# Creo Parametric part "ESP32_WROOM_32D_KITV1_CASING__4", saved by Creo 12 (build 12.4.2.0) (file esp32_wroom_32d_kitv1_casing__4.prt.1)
Units: Custom; MM, KILOGRAM, SECS

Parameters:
  PTC_WM_ITERATION = "0"
  PTC_WM_VERSION = "-.0"
  PTC_WM_LIFECYCLE_STATE = "In Work"
  PTC_WM_LIFECYCLE = "MO_CADDocument"
  PTC_WM_CREATED_BY = "Maximilian Roepper (Z0017RMS: MO)"
  PTC_WM_CREATED_ON = "18-Sep-26 11:36:42 AM"
  PTC_WM_MODIFIED_BY = "Maximilian Roepper (Z0017RMS: MO)"
  PTC_WM_MODIFIED_ON = "18-Sep-26 11:36:46 AM"
  PDMLINKNUMBER = "PDM000071455080"
  PTC_WM_NAME = "esp32_wroom_32d_kitv1_casing__4.prt"
  PTC_WM_NUMBER = "PDM000071455080"

Other parameters: WEIGHT, WEIGHT_FACTOR, WEIGHT_ADD, _MASS_TEMP, _DIFF_TEMP, MC_ERRORS, SUPPLIER

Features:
  1. coordinate system
  2. datum plane "PRT_YZ"
  3. datum plane "PRT_XY"
  4. datum plane "PRT_XZ"
  5. coordinate system
  6. datum axis
  7. datum axis
  8. datum axis
  9. coordinate system
  10. imported feature
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
Other named items: PRT, SIEMENS_MO, DRW_VIEW_ORG, PRT_X, PRT_Y, PRT_Z, CS0, ROUGH_GROB

Layers: 00_STD_CSYS-KSYS, 01_STD_PLANES-EBENEN, 02_STD_AXES-ACHSEN, 03_STD_CSYS-KSYS, 24_IMPORT_FEAT-IMPORT_KE

Surfaces: 6 plane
